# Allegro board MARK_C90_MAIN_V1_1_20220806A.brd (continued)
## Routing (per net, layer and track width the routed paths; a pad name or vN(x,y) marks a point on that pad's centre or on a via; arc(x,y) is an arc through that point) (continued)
LDR1: length 48.8
  TOP w0.102: J8.6 21.04,57.96 21.64,57.36 v1(23.42,57.36) 24.24,57.36 24.51,57.09 25.51,57.09 C73.1 26.3,57.07 TP20.1
  L2_PWR w0.102: v1(30.72,89.88) 21,80.17 19.48,80.17 17.4,78.09 17.4,63.38 v1(23.42,57.36)
  BOTTOM w0.102: U4.P15 v1(30.72,89.88)
LED_G: length 50.2
  TOP w0.102: v1(41.15,71.58) 41.91,70.82 41.91,68.89 39.9,66.88 39.9,57.18 36.12,53.4 29.94,53.4 29.44,53.9 29.44,55.33 TP21.1 26.67,58.1 R56.2
  BOTTOM w0.102: U4.C6 38.52,84.03 38.98,84.03 39.19,83.82 41.36,83.82 41.68,83.49 41.68,72.12 v1(41.15,71.58)
LED_R: length 46.5
  TOP w0.102: R54.1 v1(28.6,53.78) ; v1(37.74,71.69) 37.24,71.18 37.24,68.71 39.67,66.27 39.67,57.36 35.94,53.63 30.25,53.63 v1(30.1,53.78)
  BOTTOM w0.102: v1(28.6,53.78) v1(30.1,53.78) ; U4.C5 38.5,83.36 40.36,83.36 41.22,82.5 41.22,73.67 39.81,72.26 38.01,72.26 37.74,71.99 v1(37.74,71.69)
LINK/ACT: length 8.6
  TOP w0.102: R99.1 v1(7.77,80.07)
  BOTTOM w0.102: J3.11 8.54,85.56 8,85.02 8,83.91 9.03,82.88 9.03,80.61 8.48,80.07 v1(7.77,80.07) 7.77,79.66 TP5.1
M0: length 20.4
  BOTTOM w0.102: U12.19 34.98,66.09 34.44,66.63 34.44,68.49 34.84,68.88 R42.1 34.42,69.33 34.42,70.6 37.22,73.4 39.33,73.4 40.08,74.15 40.08,81.16 U4.A3
M1: length 20.9
  BOTTOM w0.102: U4.B3 39.18,82.1 39.57,82.1 39.88,81.79 39.88,81.69 40.31,81.26 40.31,74.05 39.43,73.17 37.38,73.17 35.37,71.17 35.37,69.33 R43.1 34.8,67.85 34.8,66.86 35.07,66.59 U12.20
M2: length 19.4
  BOTTOM w0.102: U4.B4 39.57,82.41 40.54,81.44 40.54,73.96 39.52,72.94 37.53,72.94 36.3,71.71 36.3,69.36 R44.2 36.21,68.31 U12.1
M3: length 20.4
  BOTTOM w0.102: U4.B5 39.17,82.73 40.35,82.73 40.77,82.31 40.77,73.86 39.62,72.71 37.68,72.71 37.08,72.12 37.08,71.28 37.24,71.13 37.24,69.37 R45.2 36.71,67.86 U12.2
M4: length 20.7
  BOTTOM w0.102: U4.A5 40.34,83.06 41,82.4 41,73.77 39.71,72.49 37.83,72.49 37.34,71.99 37.34,71.43 38.2,70.57 38.2,69.36 R46.2 38.19,68.38 37.74,68.38 37.21,67.85 U12.3
M5: length 20.7
  BOTTOM w0.102: U4.B6 38.95,83.59 41.26,83.59 41.45,83.4 41.45,73.58 40.11,72.24 40.11,69.36 R47.2 38.91,68.15 38.02,68.15 37.71,67.84 U12.4
M6: length 21.7
  BOTTOM w0.102: U4.B7 39.03,84.36 39.33,84.05 41.45,84.05 41.91,83.59 41.91,71.79 41.07,70.94 41.07,69.36 R48.2 39.59,67.88 38.33,67.88 38.21,67.76 U12.5
M7: length 21.3
  BOTTOM w0.102: U12.6 39.25,66.59 R49.2 42.14,69.48 42.14,83.68 41.54,84.28 39.56,84.28 U4.A7
MCLK: length 2.1
  BOTTOM w0.152: R57.2 36.33,79.32 36.89,79.87 U4.E1
MICBIAS: length 17
  TOP w0.254: R20.2 41.91,79.44 41.91,83.12 41.1,83.93 36.5,83.93 34.97,82.4 C69.1 C68.1 32.94,82.73 32.26,82.73 32.13,82.61 v1(31.5,82.61)
  BOTTOM w0.254: v1(31.5,82.61) 31.5,82.21 U4.P3
MICNL: length 21.1
  TOP w0.152: J1.1 39.38,70.02 39.83,69.58 40.1,69.58 40.36,69.83 40.36,70.67 38.94,72.09 38.94,72.63 C22.1 38.94,73.28 38.94,73.64 39.83,74.53 39.83,74.8 R15.1 39.64,75.85 R18.1 39.83,76.35 39.83,79.25 40.77,80.19 40.77,82.35 40.18,82.94 37.21,82.94 36.47,82.2 C71.2
MICPL: length 22.6
  TOP w0.152: J1.2 39.38,68.77 39.83,69.22 40.25,69.22 40.71,69.68 40.71,70.82 39.29,72.24 39.29,72.63 C22.2 39.29,73.28 39.29,73.49 40.18,74.38 40.18,74.8 R19.2 40.37,75.85 R18.2 40.18,76.35 40.18,79.11 41.12,80.05 41.12,82.5 40.33,83.29 37.06,83.29 36.22,82.45 C70.2
MINNL: length 6.7
  TOP w0.152: C71.1 35.46,81.19 34.87,80.6 32.34,80.6 31.88,81.06 31.88,81.57 31.6,81.85 31.13,81.85 v1(30.72,81.43)
  BOTTOM w0.152: U4.P2 v1(30.72,81.43)
MINPL: length 5
  TOP w0.152: C70.1 35.21,81.44 34.73,80.96 32.49,80.96 32.23,81.21 32.23,81.71 32.01,81.93 v1(32.01,82.08)
  BOTTOM w0.152: U4.N3 v1(32.01,82.08)
MSC0_CLK_PB04: length 3.9
  TOP w0.203: D3.1 18.06,89.52 v1(18.06,90.1)
  BOTTOM w0.102: J32.5 18.28,90.32 v1(18.06,90.1) 18.06,89.08 R207.1
MSC0_CMD_PB05: length 27.2
  TOP w0.102: 19.6,90.81 R210.2
  TOP w0.203: 19.6,90.81 v1(19.6,90.1) 19.6,89.54 D4.1
  BOTTOM w0.102: J32.3 20.48,90.98 v1(19.6,90.1) 20.57,89.13 23.04,89.13 24.03,90.12 24.03,92.67 25.9,94.54 25.9,94.54 26.11,94.75 34.71,94.75 35.62,93.84 35.62,93.39 35.62,91.11 35.59,91.08 U4.G17
MSC0_D0_PB00: length 30.7
  TOP w0.203: D5.1 16.52,89.51 v1(16.52,90.1) 16.51,90.11 R209.2
  BOTTOM w0.102: J32.7 16.08,90.54 v1(16.52,90.1) 16.52,88.95 17.27,88.2 23.11,88.2 24.74,89.83 24.74,92.37 26.4,94.04 34.42,94.04 34.91,93.55 34.91,91.11 34.94,91.07 U4.H16
MSC0_D1_PB01: length 31
  TOP w0.102: R211.2 14.98,90.84 v1(14.98,90.35)
  BOTTOM w0.102: J32.8 v1(14.98,90.35) TP45.1 14.98,89.98 D6.1 16.99,87.97 23.2,87.97 24.97,89.73 24.97,92.28 26.5,93.81 34.32,93.81 34.62,93.52 34.62,89.88 U4.J15
MSC0_D2_PB02: length 25.5
  TOP w0.203: R212.2 22.68,90.78 v1(22.68,90.1) 22.68,89.57 D7.1
  BOTTOM w0.102: J32.1 v1(22.68,90.1) 22.76,90.02 23.28,90.02 23.57,90.31 23.57,92.86 25.78,95.07 25.91,95.21 34.9,95.21 36.13,93.98 36.13,90.55 35.91,90.34 35.91,89.88 U4.G15
MSC0_D3_PB03: length 26.5
  TOP w0.203: R213.2 21.14,90.79 v1(21.14,90.1) 21.14,89.56 D8.1
  BOTTOM w0.102: J32.2 21.58,90.54 v1(21.14,90.1) 21.88,89.36 22.95,89.36 23.8,90.22 23.8,92.77 26.01,94.98 34.81,94.98 35.9,93.89 35.9,91.16 35.92,91.13 35.92,90.72 35.59,90.39 U4.G16
MVDD: length 2
  TOP w0.254: U7.B5 v1(23.06,74.13)
  BOTTOM w0.254: C39.1 23.39,74.13 v1(23.06,74.13) 22.86,74.33 R27.2
PHY_AVDDL_REG: length 3
  BOTTOM w0.254: C74.1 C76.1 30.77,91.98 30.77,90.58 U4.R16
PHY_LED0: length 24.6
  TOP w0.102: v1(30.07,87.93) 29.71,87.57 27.42,87.57 27.31,87.69 22.4,87.69 16.46,81.74 11.53,81.74 9.85,80.07 R99.2
  BOTTOM w0.102: U4.R13 v1(30.07,87.93)
PHY_LED1: length 27
  TOP w0.102: R100.2 11.7,81.51 16.55,81.51 22.5,87.46 27,87.46 27.18,87.28 30.02,87.28 30.48,87.74 30.48,89 v1(30.71,89.23)
  BOTTOM w0.102: U4.R15 v1(30.71,89.23)
PHY_RST: length 39.1
  TOP w0.102: C176.1 27.04,89.32 R52.1 ; C176.1 27.56,87.93 v1(29.42,87.93) ; C176.1 26.53,87.94 24,87.94 23.49,88.45 23.49,92.77 22.73,93.53 v1(22.73,94.34)
  BOTTOM w0.102: v1(22.73,94.34) 23.4,94.34 25.4,96.35 35.43,96.35 39.17,92.61 39.45,92.61 39.79,92.27 39.79,88.08 39.55,87.84 39.55,87.01 U4.A11 ; U4.T13 v1(29.42,87.93)
POR_CTRL: length 2
  BOTTOM w0.102: R343.2 33.64,91.98 U4.K16
PWDN_PA19: length 24
  TOP w0.102: v1(36.57,80.78) 36.75,80.59 36.75,74.45 33.1,70.8 24.82,70.8 24.59,71.02 24.59,71.84 R33.2 25.08,72.87 U7.A4
  BOTTOM w0.102: U4.E2 v1(36.57,80.78)
RD_N: length 25.7
  BOTTOM w0.104: U4.U17 27.11,90.86 23.43,87.18 15.23,87.18 14.07,88.34 13.61,88.34 13.5,88.44 13.5,88.7 13.4,88.8 13.19,88.8 13.09,88.7 13.09,88.44 12.98,88.34 12.77,88.34 12.67,88.44 12.67,88.7 12.57,88.8 12.36,88.8 12.25,88.7 12.25,88.44 12.15,88.34 11.94,88.34 11.84,88.44 11.84,88.7 11.73,88.8 11.52,88.8 11.42,88.7 11.42,88.44 11.32,88.34 11.11,88.34 11,88.44 11,88.7 10.9,88.8 10.69,88.8 10.59,88.7 10.59,88.44 10.48,88.34 10.27,88.34 10.17,88.44 10.17,88.65 10.07,88.75 9.86,88.75 9.75,88.65 9.75,88.44 9.65,88.34 9.06,88.34 J3.5
RD_P: length 25.7
  BOTTOM w0.104: J3.6 13.96,88.06 15.11,86.9 23.55,86.9 27.22,90.58 28.94,90.58 28.96,90.55 29.22,90.55 29.52,90.86 U4.T17
RX_DV: length 5.7
  TOP w0.102: R313.1 27.57,87.05 30.08,87.05 30.68,87.65 30.68,87.9 v1(31.36,88.58)
  BOTTOM w0.102: U4.P14 v1(31.36,88.58)
RXD3: length 6.5
  TOP w0.102: R314.1 27.53,89.76 27.53,88.55 27.74,88.35 29.84,88.35 v1(30.09,88.59) 30.1,88.61 R315.1
  BOTTOM w0.102: U4.R14 30.1,88.61 30.1,88.61 v1(30.09,88.59)
RZQ: length 3.8
  BOTTOM w0.102: R75.1 40.74,86.75 40.18,86.19 39.19,86.19 38.96,85.96 37.84,85.96 U4.D9
SD0_CD_N: length 53.2
  TOP w0.102: Q1.1 16.4,95.83 15.37,94.8 14.66,94.8 14.27,94.42 14.27,93.7 v1(13.84,93.27) C150.2 13.27,93.25 R214.2 11.71,93.25 11.37,93.59 11.37,95.37 11.81,95.82 v1(11.81,97.34)
  BOTTOM w0.102: U4.C10 38.53,86.65 39.62,86.65 39.83,86.85 39.83,87.74 40,87.91 40,92.42 39.5,92.92 39.19,92.92 35.51,96.6 25.33,96.6 23.83,95.1 15.8,95.1 13.31,97.59 12.06,97.59 v1(11.81,97.34) ; v1(13.84,93.27) 13.88,93.23 J32.9 13.88,90.36 D9.1
SENSOR_MCLK: length 12
  TOP w0.102: U7.C2 25.86,75.12 26.19,75.44 26.72,75.44 27,75.72 27,76.54 27.46,76.99 32.49,76.99 33.27,77.78 v1(35.56,77.78)
  BOTTOM w0.152: R57.1 v1(35.56,77.78)
SENSOR_RESET: length 26.7
  TOP w0.102: U7.C4 24.13,74.47 23.77,74.1 23.77,73.65 24.12,73.29 C35.2 24.12,71.32 R34.2 24.14,70.91 24.49,70.57 33.23,70.57 36.98,74.32 36.98,81.2 v1(37.21,81.43)
  BOTTOM w0.102: U4.E3 v1(37.21,81.43)
SFC_CS_N: length 19.4
  TOP w0.203: R12.1 13.1,80.21 v1(13.1,80.85)
  BOTTOM w0.102: U4.T4 29.56,82.23 23.37,82.23 21.21,80.07 13.88,80.07 v1(13.1,80.85) 13.1,81.24 13,81.34 U13.1
SFC_SCLK: length 10
  BOTTOM w0.102: U13.6 21.01,83.88 21.39,84.26 28.7,84.26 28.93,84.03 29.84,84.03 30.17,83.71 U4.R6
SFC_SIO0: length 13.1
  BOTTOM w0.102: U13.5 20.46,85.15 19.76,84.44 19.76,82.4 20.02,82.15 22.02,82.15 22.93,83.06 U4.U5
SFC_SIO1: length 20.5
  BOTTOM w0.102: U13.2 13.06,82.61 13.54,82.13 13.54,80.73 13.98,80.3 21.05,80.3 21.91,81.16 23.23,82.48 29.35,82.48 29.6,82.73 30.07,82.73 U4.R5
SFC_SIO2: length 20.8
  BOTTOM w0.102: U4.T5 29.55,83.06 29.23,82.73 23.16,82.73 20.95,80.52 14.07,80.52 13.77,80.83 13.77,83.17 13.06,83.88 U13.3
SFC_SIO3: length 9.4
  BOTTOM w0.102: U13.7 22.16,82.61 22.92,83.37 29.4,83.37 U4.T6
SID: length 3
  TOP w0.102: R36.2 R35.2 23.4,73.63 U7.A5
SMB0_SCK: length 23.5
  TOP w0.102: v1(36.2,80.14) 36.53,79.81 36.53,74.55 34.06,72.08 30.03,72.08 29.71,72.4 27.86,72.4 27.39,71.93 26.41,71.93 R30.2 24.86,73.48 U7.A3
  BOTTOM w0.102: v1(36.2,80.14) 35.91,80.42 35.91,82.1 35.61,82.41 U4.J4
SMB0_SDA: length 21
  TOP w0.102: U7.B3 25.22,74.1 25.22,73.49 25.88,72.83 26.43,72.83 R32.2 27.47,72.33 27.76,72.62 29.81,72.62 30.12,72.31 33.96,72.31 36.3,74.64 36.3,79.26 v1(35.69,79.87)
  BOTTOM w0.102: v1(35.69,79.87) 35.14,79.87 34.56,80.46 U4.J1
SOC_0V8: length 28
  TOP w0.203: R5.2 21.6,98.9 C6.2 20.05,98.9 19.66,98.51 19.66,96.17 20.78,95.05 23.25,95.05 23.75,94.55
  TOP w0.254: v1(30.71,82.73) 30.71,83.38 v1(31.37,84.03)
  TOP w0.305: v1(31.37,81.43) 31.37,79.93 C86.1
  L2_PWR w0.254: v1(31.37,81.43) 31.37,82.08 v1(30.71,82.73)
  BOTTOM w0.102: v1(32.67,83.38) 32.66,83.38 ; v1(33.97,88.58) 33.96,88.58 ; v1(34.62,84.68) 34.62,84.68 ; v1(31.37,85.98) 31.37,85.98 ; 34.62,87.28 v1(34.62,87.28) ; v1(34.62,85.33) 34.62,85.33 ; v1(34.62,86.63) 34.62,86.63 ; v1(31.37,85.33) 31.37,85.33 ; v1(33.97,83.38) 33.96,83.38
  BOTTOM w0.152: U4.J5 v1(33.97,83.38) ; U4.N8 v1(31.37,85.33) ; 34.62,85.33 U4.H9 ; U4.N6 v1(31.37,84.03) U4.N7 ; 33.96,83.38 U4.K5 ; 31.37,85.33 U4.N9 v1(31.37,85.98) ; 34.62,86.63 U4.H11 v1(34.62,87.28) ; v1(33.97,88.58) U4.J13 v1(34.62,88.58) U4.H13 ; v1(32.02,83.38) U4.M5 32.66,83.38 ; U4.H12 34.62,87.28 ; v1(34.62,85.33) U4.H8 34.62,84.68 ; v1(34.62,86.63) U4.H10 ; v1(33.31,89.23) U4.L15 ; 31.37,85.98 U4.N10 ; U4.L5 v1(32.67,83.38) ; U4.H6 v1(34.62,83.38) U4.H5 ; U4.H7 v1(34.62,84.68) ; 33.96,88.58 U4.K13
  BOTTOM w0.254: U4.R4 v1(30.71,82.73) ; U4.N2 v1(31.37,81.43)
SOC_3V3: length 94.3
  TOP w0.203: R3.2 14.09,66.83 C5.1 16.1,66.83
  TOP w0.254: v1(38.51,82.08) 39,82.08 C96.1 ; 16.89,79.24 15.93,80.19 R12.2
  TOP w0.305: 12.3,94.27 R214.1 ; v1(19.71,81.34) C17.2 ; C65.1 29.33,83.47 v1(30.71,82.08) ; C65.1 C189.1 ; C65.1 v1(30.86,84.77)
  TOP w0.406: R52.2 R314.2 R51.2 v1(26.02,91.61) ; C144.1 35.69,89.44 v1(35.34,89.09)
  TOP w0.508: 12.3,94.27 C150.1 13.29,95.16 C149.1 C148.1 14.43,96.08 Q1.2 14.5,96.37 15.39,97.26 17.35,97.26 v1(18.29,96.32)
  L2_PWR w0.305: v1(38.51,82.08) 38.06,82.54 37.57,82.54 35.15,80.12 30.51,80.12 29.41,81.21 29.41,82.94 v1(28.55,83.8)
  L2_PWR w0.508: v1(41,92.87) 39.79,94.08 v1(39.28,94.08) 35.98,94.08 35.34,93.44 ; v1(26.02,91.61) 23,91.61 v1(18.29,96.32) ; v1(26.02,91.61) 30,95.59 33.2,95.59 35.34,93.44 ; v1(26.02,91.61) 26.02,88.97 25.37,88.32 v1(25.37,86.49) v1(25.37,85.88) ; v1(35.34,89.09) 35.34,93.44
  BOTTOM w0.254: U4.R3 v1(30.71,82.08) ; R53.1 35.76,97.59 v1(39.28,94.08) ; v1(30.86,84.77) 30.86,85.48 U4.P9 ; v1(35.34,89.09) 34.48,89.09 U4.J14 ; v1(41,92.87) 41.69,92.17 R60.2 41.69,87.99 R59.2 ; U4.C4 v1(38.51,82.08)
  BOTTOM w0.406: U13.8 v1(19.71,81.34) ; R23.2 R16.2 26.73,86.49 v1(25.37,86.49)
  vias: v1(27.43,68.08) v1(27.53,67.16) v1(28.52,67.29)
SOC_DDR: length 20.1
  TOP w0.203: R346.2 40,90.1 39.57,90.53 37.9,90.53 ; TP3.1 35.26,93.99 33.23,93.99 33.03,94.19 33.03,94.89 32.86,95.06 32.04,95.06 31.53,94.55 C15.1 31.24,95.55 R11.2
  TOP w0.406: v1(35.92,84.68) v1(35.92,84.03) v1(36.57,84.68)
  BOTTOM w0.102: 35.92,87.28 v1(35.92,87.28) ; 36.57,84.68 v1(36.57,84.68) ; 35.92,84.68 v1(35.92,84.68)
  BOTTOM w0.152: U4.F10 v1(35.92,85.98) 35.92,85.98 U4.F9 ; U4.E7 v1(36.57,84.68) ; U4.F6 v1(35.92,84.03) 35.92,84.03 U4.F7 v1(35.92,84.68) ; U4.E12 v1(36.57,87.28) 36.57,87.28 U4.E11 ; U4.F12 v1(35.92,87.28) ; U4.F11 35.92,87.28 ; U4.F8 35.92,84.68 ; U4.E9 36.57,85.98 v1(36.57,85.98) U4.E10 ; U4.E8 36.57,84.68
SPEAK_EN_PB31: length 58.2
  TOP w0.102: v1(11.3,97.85) 10.67,97.21 10.67,91.12 8.92,89.36 8.92,88.06 7.47,86.61 7.47,84.79 8,84.26 9.54,84.26 v1(10.04,83.76)
  BOTTOM w0.102: R22.1 10.04,83.76 v1(10.04,83.76) ; U4.B10 39,86.31 39.12,86.42 39.95,86.42 40.08,86.54 40.08,87.62 40.25,87.79 40.25,92.67 39.73,93.2 39.24,93.2 35.61,96.83 25.24,96.83 23.74,95.33 15.89,95.33 13.38,97.85 v1(11.3,97.85)
SPEED: length 11.2
  TOP w0.102: v1(6.35,79.43) 6.68,79.1 R100.1
  BOTTOM w0.102: v1(6.35,79.43) 7.39,80.47 8.53,80.47 8.8,80.74 8.8,82.79 7.77,83.81 7.77,84.74 7.46,85.06 J3.12
TD_N: length 25
  BOTTOM w0.104: J3.8 13.33,87.06 14.27,86.11 23.61,86.11 27.68,90.18 29.07,90.18 U4.U16
TD_P: length 25
  BOTTOM w0.104: U4.T16 29.52,90.21 29.22,89.9 27.79,89.9 23.72,85.83 14.16,85.83 13.22,86.78 12.81,86.78 12.71,86.67 12.71,86.52 12.6,86.42 12.4,86.42 12.29,86.52 12.29,86.67 12.19,86.78 11.98,86.78 11.88,86.67 11.88,86.52 11.77,86.42 11.56,86.42 11.46,86.52 11.46,86.67 11.35,86.78 11.15,86.78 11.04,86.67 11.04,86.52 10.94,86.42 10.73,86.42 10.63,86.52 10.63,86.67 10.52,86.78 10.31,86.78 10.21,86.67 10.21,86.55 10.1,86.44 9.9,86.44 9.79,86.55 9.79,86.67 9.69,86.78 9.06,86.78 J3.9
UART1_RXD: length 46.5
  TOP w0.102: v1(10.16,94.29) 10.41,94.04 10.41,91.24 8.69,89.52 8.69,88.15 7.24,86.7 7.24,84.51 7.87,83.88 v1(9.02,83.88)
  BOTTOM w0.102: J3.13 9.02,84.38 v1(9.02,83.88) ; v1(10.16,94.29) 10.84,94.97 14.64,94.97 15.42,94.19 19.84,94.19 20.75,93.28 23.62,93.28 25.78,95.43 35,95.43 36.35,94.08 36.35,90.32 U4.F16
UART1_TXD: length 47.1
  TOP w0.102: v1(6.98,84.06) 6.98,86.77 8.46,88.25 8.46,89.67 10.16,91.37 10.16,93.66 v1(9.52,94.29)
  BOTTOM w0.102: v1(9.52,94.29) 10.44,95.21 14.73,95.21 15.51,94.42 19.93,94.42 20.85,93.5 23.53,93.5 25.69,95.66 35.09,95.66 36.58,94.17 36.58,90.11 36.24,89.76 U4.F15 ; v1(6.98,84.06) J3.14
USB_DM: length 26.6
  BOTTOM w0.13: U4.U1 29.06,80.48 28.52,80.48 28.36,80.32 28.01,80.32 27.85,80.48 27.49,80.48 27.33,80.32 26.97,80.32 26.81,80.48 24.16,80.48 19.28,75.6 19.28,69.45 19.95,68.78 20.13,68.78 20.29,68.94 20.47,68.94 20.66,68.76 20.66,68.57 20.5,68.42 20.5,68.23 20.68,68.05 20.86,68.05 21.02,68.21 21.21,68.21 21.39,68.03 21.39,67.84 21.23,67.68 21.23,67.5 21.44,67.29 22.22,67.29 22.52,67.59 22.52,68.5 22.98,68.95 24.13,68.95 U14.3
USB_DP: length 26.6
  BOTTOM w0.13: U14.2 22.99,65.45 22.61,65.84 22.61,66.61 22.22,66.99 21.31,66.99 18.97,69.32 18.97,75.72 24.04,80.79 29.42,80.79 U4.T2
VCM: length 3.7
  TOP w0.305: v1(30.71,80.78) 30.71,80.31 C66.1 C67.1
  BOTTOM w0.254: U4.R2 v1(30.71,80.78)
VOTP: length 2.5
  TOP w0.254: U7.E7 v1(21.46,76.42)
  BOTTOM w0.305: TP24.1 20.45,75.4 v1(21.46,76.42)
WIFI_3V3: length 3.9
  BOTTOM w0.508: R68.2 C89.1 27.77,70.93 C84.1 27.95,70.75 Q2.3
WIFI_PWR_EN: length 35.4
  L2_PWR w0.102: v1(37.87,86.63) 40.43,86.63 41.96,85.1 41.96,72.52 42.24,72.24 42.24,68.66 41.88,68.31 41.88,68.12 41.88,68.12 41.88,65.77 41.25,65.13 v1(32.92,65.13)
  BOTTOM w0.102: R70.1 32.63,65.08 32.87,65.08 v1(32.92,65.13) ; U4.C11 v1(37.87,86.63)
ZQ: length 5.2
  BOTTOM w0.102: U4.F13 37.4,88.26 37.86,88.72 37.86,91.73 R345.1
N16068033: length 7.6
  TOP w0.102: U9.4 14.73,84.18 12.5,86.41 J4.2
N16068049: length 4.7
  TOP w0.102: U9.2 12.19,84.38 11.42,85.16 J4.1
N16494121: length 5.2
  BOTTOM w0.533: C83.1 C97.2 8,63.56 arc(8.21,64.05) 8.7,64.25 U14.5
N16494125: length 1.9
  BOTTOM w0.533: C83.2 8,60.83 L5.1 J9.3
N16658117: length 6.1
  BOTTOM w0.102: Q3.3 32.38,70.54 30.01,68.16 Q2.1 30.01,67.28 C91.1 29.58,65.86 R69.1
N16658257: length 2.4
  BOTTOM w0.102: R70.2 R71.2 33.33,67.29 Q3.1
N16680846: length 3.1
  TOP w0.254: U10.3 23.58,62.59 24.26,61.91 24.26,61.25 23.9,60.89 R38.2
N16681558: length 2.4
  TOP w0.254: C50.1 R40.2 30.01,62.59 U11.3
N16842331: length 7.9
  TOP w0.102: J8.3 19.77,54.47 20.02,54.72 22.76,54.72 23.7,53.78 TP18.1 R54.2
N17912916: length 3.6
  TOP w0.203: C5.2 14.09,65.83 R3.1 14.01,65.74 R4.2 13.07,64.8 12.86,65 U1.5
N17913000: length 2.6
  TOP w0.203: C3.1 14.94,69.13 R1.2 13.14,69.13 12.86,68.85 U1.1
N17913512: length 2.8
  TOP w0.203: C10.1 21.62,95.67 R2.2 22.41,96.72 U2.1
N17913867: length 2.9
  TOP w0.203: C14.1 37.65,60.57 R7.2 35.52,60.57 35.32,60.37 U3.1
N17913918: length 5.2
  TOP w0.203: U3.5 35.32,55.56 R9.2 36.65,56.33 R8.1 37.65,57.25 C11.2
N17914253: length 2.9
  TOP w0.203: C20.1 33.55,94.57 R10.2 33.55,96.7 33.35,96.9 U5.1
N17914314: length 3.9
  TOP w0.203: U5.5 29.42,96.9 29.22,96.7 R13.2 30.21,95.58 R11.1 30.24,95.55 C15.2
N17923584: length 2.9
  TOP w0.254: 41.41,77.89 R20.1
  TOP w0.305: R19.1 41.41,74.99 C24.1 C23.1 41.41,77.89
N17923959: length 2.9
  BOTTOM w0.102: R21.1 11.56,82.21 R22.2 9.69,81.37 U6.1
N17923983: length 8.1
  BOTTOM w0.305: J2.2 9.59,69.93 10.44,69.93 10.92,70.41 10.92,70.44 10.97,70.49 10.97,74.28 11.64,74.95 U6.5
N17923995: length 7.4
  BOTTOM w0.305: J2.1 9.61,70.37 10.24,70.37 10.54,70.67 10.54,74.23 9.69,75.07 U6.8
N17924016: length 2.7
  BOTTOM w0.305: U6.4 11.64,79.85 12.45,79.05 R26.1
N17924026: length 0.8
  BOTTOM w0.305: R26.2 C27.1
N17924036: length 0.8
  BOTTOM w0.305: R24.2 C26.1
N17924072: length 3.8
  BOTTOM w0.305: R24.1 12.57,78.16 10.99,79.74 U6.3
N17926744: length 1.5
  TOP w0.254: C32.2 20.55,75.77 U7.D7
N17926746: length 1.6
  TOP w0.254: C33.2 20.61,77.07 U7.F7
N17992613: length 3.9
  TOP w0.203: C6.1 20.62,99.92 R5.1 21.63,99.93 R6.1 22.75,100.92 22.95,100.72 U2.5
N18040120: length 1.5
  TOP w0.102: v1(29.42,89.23) 29.42,89.76 R312.1
  BOTTOM w0.102: U4.T15 v1(29.42,89.23)
N18040755: length 24.5
  BOTTOM w0.102: R207.2 19.63,88.55 22.96,88.55 24.38,89.97 24.38,92.52 26.25,94.39 34.57,94.39 35.26,93.7 35.26,89.88 U4.H15
N18061971: length 1.6
  TOP w0.203: U10.4 23.76,65.59 C52.1
N18083960: length 1.7
  BOTTOM w0.254: R16.1 28.14,86.31 U4.T10
N18093878: length 2.8
  BOTTOM w0.102: U4.R10 30.19,86.31 29.89,86 28.76,86 R23.1
N179301303: length 6.2
  TOP w0.102: J8.4 19.77,58.01 20.73,57.05 22.37,57.05 R55.2

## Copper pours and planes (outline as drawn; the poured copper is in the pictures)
2V8 on TOP: 19.63,71.51 19.63,66.68 20.02,66.3 20.02,64.95 20.22,64.75 21.41,64.75 21.51,64.85 21.51,66.53 20.55,67.49 20.55,71.35 20.32,71.58 19.71,71.58
AGND on TOP: 18.24,76.79 18.24,65.08 18.95,64.37 19.71,64.37 19.79,64.45 19.79,66.17 19.41,66.55 19.41,74.02 19.68,74.3 20.32,74.3 20.42,74.4 20.42,74.66 19.71,75.37 19.71,77.17 19.58,77.3 18.75,77.3
VCC_5V on TOP: 24.94,101.45 29.01,101.45 30.68,99.78 30.68,98.46 30.48,98.25 28.5,98.25 26.87,99.88 25.65,99.88 25.25,99.47 24.54,99.47 24.49,99.52 24.49,101
VCC_5V on TOP: 17.01,52.85 16.66,53.19 16.66,56.67 10.16,63.18 10.16,64.07 6.22,68 6.22,69.15 6.35,69.27 8,69.27 10.92,66.35 11.81,66.35 12.06,66.1 12.06,64.32 17.4,58.99 18.67,58.99 18.85,58.81 18.85,52.94 18.76,52.85
VCC_5V on TOP: 33.73,57.72 32.51,57.72 31.55,56.75 31.55,54.92 31.75,54.72 33.68,54.72 33.88,54.92 33.88,57.56
VCC_5V on BOTTOM: 8.94,92.77 10.72,92.77 11.07,92.41 11.07,90.28 10.87,90.07 7.11,90.07 6.81,89.77 5.54,89.77 5.44,89.87 5.44,90.96 5.97,91.5 8.59,91.5 8.84,91.75 8.84,92.67
VCC_5V on BOTTOM: 22.1,58.63 24.64,58.63 25.86,57.41 27.94,57.41 29.67,55.68 33.17,55.68 33.38,55.89 34.75,55.89 35.05,56.19 35.05,58.63 35.28,58.86 38.99,58.86 39.75,59.62 39.75,64.75 39.55,64.95 38.99,64.95 38.91,65.03 38.91,65.18 38.96,65.23 39.93,65.23 40.03,65.34 40.51,65.34 40.82,65.64 41.91,65.64 42.06,65.49 42.06,58.63 40.64,57.21 38.15,57.21 35.08,54.13 29.54,54.13 27.69,55.99 24.23,55.99 23.62,55.38 23.62,53.91 22.99,53.27 16.84,53.27 16.64,53.47 16.64,54.59 16.81,54.77 20.78,54.77 22.05,56.04 22.05,58.58
VCC_5V on L2_PWR: 28.3,102.19 17.93,102.19 6.22,90.48 6.22,68.13 6.73,67.62 8.76,67.62 10.11,68.97 10.11,89.67 19.94,99.5 28.83,99.5 29.21,99.88 29.21,101.28
DOVDD1V8 on TOP: 35.46,61.7 34.85,61.7 34.77,61.78 34.77,66.58 32.28,69.07 32.28,69.63 32.41,69.75 33.5,69.75 35.92,67.34 35.92,64.5 36.58,63.84 38.4,63.84 38.79,63.46 38.79,61.78 38.48,61.47 38.02,61.47 37.03,62.46 36.22,62.46
DOVDD1V8 on L2_PWR: 35.81,68.64 32.38,68.64 32.13,68.89 32.13,69.6 32.31,69.78 32.87,69.78 37.29,74.2 37.29,78.37 37.11,78.54 28.27,78.54 27.43,79.38 27.43,84.13 28.12,84.82 29.9,84.82 30.33,84.39 30.33,80.73 31.01,80.04 35.74,80.04 37.39,81.69 37.97,81.69 38.15,81.51 38.15,73.72 36.58,72.14 36.58,69.4
SOC_0V8 on TOP: 32.46,90.84 32.46,89.26 33.83,87.89 33.83,84.05 33.5,83.72 32.56,83.72 32.11,84.18 32.11,86.87 31.8,87.18 31.37,87.18 31.09,86.9 31.09,84.33 30.48,83.72 30.48,82.68 30.66,82.51 31.78,82.51 32.13,82.86 34.54,82.86 34.92,83.24 34.92,88.58 34.24,89.26 34.24,91.65 32.41,93.48 28.75,93.48 28.07,94.16 28.07,94.93 27.84,95.15 23.77,95.15 23.49,94.88 23.49,93.76 24.79,92.46 26.57,92.46 26.97,92.06 31.24,92.06
SOC_0V8 on BOTTOM: 33.34,89.94 34.31,88.97 34.54,88.97 34.89,88.61 35.03,88.47 35.03,88.22 34.9,88.09 34.9,87.13 35.31,86.72 35.31,86.54 34.9,86.14 34.9,85.81 35.31,85.4 35.31,85.25 34.9,84.84 34.9,84.51 35.31,84.11 35.31,83.95 34.9,83.55 34.9,83.22 35.15,82.96 35.15,82.76 35.05,82.66 32.44,82.66 31.14,83.95 31.14,86.49 31.34,86.7 32,86.7 32.08,86.62 32.08,84.13 32.64,83.57 34.32,83.57 34.42,83.67 34.42,87.53 34.06,87.89 33.76,87.89 32.54,89.11 32.54,89.85 32.63,89.94
SOC_3V3 on TOP: 12.85,72.24 15.24,72.24 16.26,73.26 16.26,79.1 24.03,86.87 26.21,86.87 26.31,86.77 26.31,84.59 26.7,84.21 28.73,84.21 29.01,84.49 29.01,85.6 29.21,85.81 29.46,85.81 30.23,85.05 30.94,85.05 31.04,84.94 31.04,84.59 30.23,83.78 30.23,82.76 29.77,82.3 21.54,82.3 17.4,78.16 17.4,61.4 18.39,60.41 20.88,60.41 21.03,60.56 21.03,61.25 20.62,61.65 20.62,63.2 20.78,63.35 21.39,63.35 21.49,63.25 21.49,61.78 22,61.27 22.73,61.27 23.24,60.76 24,60.76 25.43,62.19 25.81,62.19 26.87,63.25 27.33,63.25 27.43,63.15 27.43,61.78 27.69,61.53 29.46,61.53 30.99,63.05 30.99,66.35 30.38,66.96 27.33,66.96 27.05,67.24 27.05,68.15 27.28,68.38 31.09,68.38 32.36,67.11 32.36,60.86 29.57,58.07 28.45,58.07 27.23,59.29 17.48,59.29 15.87,60.89 15.87,70.16 15.16,70.87 14.07,70.87 13.21,70.01 12.4,70.01 12.32,70.08 12.32,71.71
SOC_3V3 on BOTTOM: 26.31,68.74 28.65,68.74 28.85,68.54 28.85,65.59 28.73,65.46 27.56,65.46 26.14,66.88 26.14,68.56
SOC_3V3 on L2_PWR: 24.46,91.42 24.46,86.32 25.15,85.63 25.5,85.63 26.37,86.49 26.37,91.57 26.14,91.8 24.84,91.8
SOC_DDR on TOP: 35.69,84.46 35.69,84.82 35.81,84.94 35.81,85.71 35.69,85.83 35.69,86.09 35.94,86.34 35.94,86.9 35.69,87.15 35.69,87.36 36.27,87.94 36.27,88.35 36.58,88.65 36.58,93.66 34.29,95.94 34.29,97.09 34.34,97.14 35.05,97.14 35.31,97.39 37.34,97.39 37.47,97.26 37.47,95.43 37.97,94.93 37.97,87.15 37.47,86.65 37.47,84.87 37.03,84.44 36.42,84.44 36.27,84.28 35.86,84.28
SOC_DDR on BOTTOM: 36.02,87.71 35.79,87.48 35.79,87.18 35.86,87.1 35.86,86.16 35.79,86.09 35.79,85.91 35.86,85.83 35.86,84.87 35.79,84.79 35.79,84.59 35.86,84.51 35.86,84.21 35.79,84.13 35.79,83.93 35.92,83.8 35.92,83.06 36.09,82.89 36.47,82.89 37.29,83.7 37.29,85.12 37.01,85.4 37.01,85.93 37.11,86.04 37.11,87.66 37.06,87.71
WIFI_3V3 on BOTTOM: 29.46,71.33 26.42,71.33 25.2,72.55 23.14,72.55 22.71,72.12 22.71,71.41 23.16,70.95 24.97,70.95 26.16,69.75 26.16,69.25 26.42,68.99 29.11,68.99 29.57,69.45 29.57,71.23
N16068033 on TOP: 8.59,86.04 12.75,86.04 14.2,84.59 14.2,82.45 14.35,82.3 14.99,82.3 15.11,82.43 15.11,85.1 13.08,87.13 8.81,87.13 8.53,86.85 8.53,86.09
N16068049 on TOP: 8.64,85.86 11.48,85.86 12.7,84.64 12.7,82.43 12.57,82.3 12.01,82.3 11.86,82.45 11.86,84.49 11.56,84.79 8.59,84.79 8.53,84.84 8.53,85.76
N17912932 on TOP: 11.28,67.72 11.28,69.88 11.46,70.06 11.46,71.74 11.4,71.79 10.49,71.79 10.16,71.46 10.16,68.21 10.67,67.7 11.25,67.7
N17913916 on TOP: 33.2,59.19 33.12,59.26 33.12,63.35 33.2,63.43 33.83,63.43 33.88,63.38 33.88,60.84 33.71,60.66 33.71,59.26 33.63,59.19
N17914320 on TOP: 32.44,99.09 34.01,99.09 34.39,99.47 36.35,99.47 36.75,99.07 36.75,98.56 36.58,98.38 34.24,98.38 34.11,98.51 32.44,98.51 32.38,98.56 32.38,99.04
N17994204 on TOP: 24.66,97.95 25.37,97.95 25.83,97.49 27.23,97.49 27.3,97.42 27.3,96.81 27.2,96.7 24.69,96.7 24.59,96.81 24.59,97.87

Small or netless copper shapes (teardrops, artwork), in the pictures only: 1 on TOP, 1 on BOTTOM, 1 on L2_PWR

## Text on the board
BOTTOM: Artwork L4_BOTTOM
Ref Des/Silkscreen Bottom: SILKSCREEN BOTTOM | SPK | 5V | VOTP | MCK | RST | MOTOR1 | SPEED | WIFI | LINK | SD_CARD | MOTOR0 | D1 | D0 | CLK | CMD | D3 | D2 | A0- | B0- | A0+ | B0+ | B1- | A1- | B1+ | A1+
User.Comments: SOLDMASK TOP | SOLDMASK BOTTOM
TOP: Artwork L1_TOP
Ref Des/Silkscreen Top: SILKSCREEN TOP | IR_CUT | SOC_0V8 | IRLED_EN | LED_G | LDR1 | LED_R | 3V3 | SOC_DDR | MIC | DOVDD1V8
L2_PWR: Artwork L2_PWR
L3_GND: Artwork L3_GND
DIMENSION: V-CUT | 100 ohm | 50 ohm | 1/4 | 4 | 4.1/6.9/4.1 | 21 | + | - | 10% | Default | MARK_C90_MAIN | 1.1 | will.liu | haisong.ding | 2022-08-06
DISPLAY_BOTTOM: PASTEMASK BOTTOM
DISPLAY_TOP: PASTEMASK TOP
User.8: FIGURE | SIZE | 8.0 | 78.74 | 91.0 | 31.5 | 33.46 | 39.37 | DRILL CHART: TOP to BOTTOM | ALL UNITS ARE IN MILS | PLATED | NON-PLATED | QTY | 401 | 240 | 2 | 4
